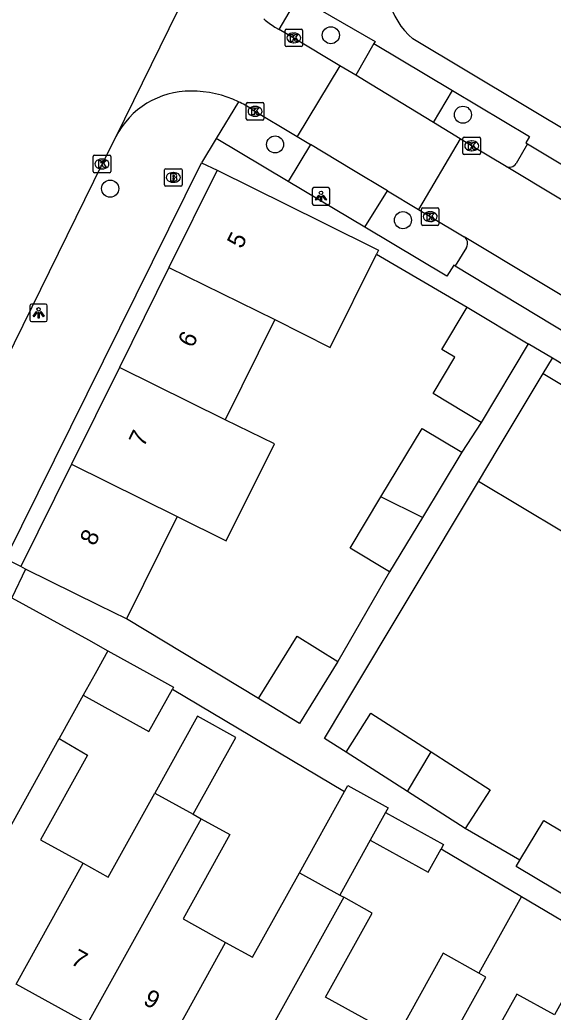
# Model space of a CAD drawing. Extents: x 160107 to 160928, y 382056 to 382918.
# Drawn here: x 160321.6 to 160352.1, y 382230.6 to 382287.4 of the extents above; entities that cross this region are included whole.
import ezdxf

# ---------------------------------------------------------------- set-up
doc = ezdxf.new("R2010")
doc.units = 0
for name, color, linetype in [('IMGEO_Boom', 7, 'Continuous'), ('IMGEO_Brandkraan', 7, 'Continuous'), ('IMGEO_Kolk', 7, 'Continuous'), ('IMGEO_Lichtpunt', 7, 'Continuous'), ('IMGEO_Muur', 7, 'Continuous'), ('IMGEO_Pand', 7, 'Continuous'), ('IMGEO_Pand_nummerreeks', 7, 'Continuous'), ('IMGEO_Parkeervlak_open', 7, 'Continuous'), ('IMGEO_Rijbaan_lokaal_open', 7, 'Continuous'), ('IMGEO_Voetpad_open', 7, 'Continuous')]:
    doc.layers.add(name, color=color, linetype=linetype)

msp = doc.modelspace()

# ---------------------------------------------------------------- linework, layer by layer
at = {"layer": 'IMGEO_Boom'}
for centre in [(160339.343, 382286.565), (160346.897, 382282.014), (160336.154, 382280.313), (160326.723, 382277.781), (160343.466, 382275.976)]:
    msp.add_circle(centre, 0.489, dxfattribs=at)
at = {"layer": 'IMGEO_Brandkraan'}
for p, q in [((160329.833, 382277.998), (160329.833, 382278.85)), ((160329.908, 382278.924), (160330.76, 382278.924)), ((160330.321, 382278.704), (160330.346, 382278.704)), ((160330.834, 382278.85), (160330.834, 382277.998)), ((160330.344, 382278.144), (160330.319, 382278.144)), ((160330.76, 382277.924), (160329.908, 382277.924))]:
    msp.add_line(p, q, dxfattribs=at)
for points in [[(160329.833, 382277.998), (160329.833, 382278.85)], [(160329.908, 382278.924), (160330.76, 382278.924)], [(160330.181, 382278.624), (160330.181, 382278.224), (160330.394, 382278.224)], [(160330.412, 382278.624), (160330.181, 382278.624)], [(160330.36, 382278.543), (160330.306, 382278.543), (160330.306, 382278.467)], [(160330.834, 382278.85), (160330.834, 382277.998)], [(160330.306, 382278.467), (160330.359, 382278.467)], [(160330.368, 382278.391), (160330.306, 382278.391), (160330.306, 382278.31)], [(160330.306, 382278.31), (160330.368, 382278.31)], [(160330.76, 382277.924), (160329.908, 382277.924)]]:
    msp.add_lwpolyline(points, dxfattribs=at)
for centre, radius, start, end in [((160329.91, 382278.848), 0.0765, 91.552, 178.448), ((160329.91, 382278.848), 0.0765, 91.552, 178.448), ((160330.361, 382278.505), 0.0379, 267.8285, 90.9355), ((160330.416, 382278.479), 0.145, 59.4692, 91.5367), ((160330.441, 382278.526), 0.0922, 285.5137, 58.1501), ((160330.758, 382278.848), 0.0765, 1.552, 88.448), ((160330.758, 382278.848), 0.0765, 1.552, 88.448), ((160329.91, 382278), 0.0765, 181.552, 268.448), ((160329.91, 382278), 0.0765, 181.552, 268.448), ((160330.369, 382278.35), 0.0404, 269.8759, 90.5077), ((160330.4, 382278.475), 0.251, 268.6676, 293.5347), ((160330.446, 382278.334), 0.105, 301.3115, 78.989), ((160330.758, 382278), 0.0765, 271.552, 358.448), ((160330.758, 382278), 0.0765, 271.552, 358.448)]:
    msp.add_arc(centre, radius, start, end, dxfattribs=at)
for centre, major_axis, ratio, start_param, end_param in [((160330.32, 382278.424), (-0.387, 0.002), 0.722429, 4.712389, 7.853982), ((160330.345, 382278.424), (-0.39, 0.002), 0.717154, 1.570796, 4.712389)]:
    msp.add_ellipse(centre, major_axis=major_axis, ratio=ratio, start_param=start_param, end_param=end_param, dxfattribs=at)
at = {"layer": 'IMGEO_Kolk'}
for p, q in [((160336.722, 382285.986), (160336.722, 382286.838)), ((160336.797, 382286.912), (160337.649, 382286.912)), ((160337.21, 382286.692), (160337.235, 382286.692)), ((160337.723, 382286.838), (160337.723, 382285.986)), ((160337.649, 382285.912), (160336.797, 382285.912)), ((160337.233, 382286.132), (160337.208, 382286.132)), ((160334.507, 382281.781), (160334.507, 382282.633)), ((160334.582, 382282.707), (160335.434, 382282.707)), ((160334.995, 382282.487), (160335.02, 382282.487)), ((160335.508, 382282.633), (160335.508, 382281.781)), ((160335.018, 382281.927), (160334.993, 382281.927)), ((160335.434, 382281.707), (160334.582, 382281.707)), ((160346.896, 382279.804), (160346.896, 382280.656)), ((160346.971, 382280.73), (160347.823, 382280.73)), ((160347.384, 382280.51), (160347.409, 382280.51)), ((160347.897, 382280.656), (160347.897, 382279.804)), ((160325.827, 382279.694), (160326.679, 382279.694)), ((160347.823, 382279.73), (160346.971, 382279.73)), ((160347.407, 382279.95), (160347.382, 382279.95)), ((160325.752, 382278.768), (160325.752, 382279.62)), ((160326.24, 382279.474), (160326.265, 382279.474)), ((160326.753, 382279.62), (160326.753, 382278.768)), ((160326.679, 382278.694), (160325.827, 382278.694)), ((160326.263, 382278.914), (160326.238, 382278.914)), ((160344.524, 382275.754), (160344.524, 382276.606)), ((160344.599, 382276.68), (160345.451, 382276.68)), ((160345.012, 382276.46), (160345.037, 382276.46)), ((160345.525, 382276.606), (160345.525, 382275.754)), ((160345.451, 382275.68), (160344.599, 382275.68)), ((160345.035, 382275.9), (160345.01, 382275.9))]:
    msp.add_line(p, q, dxfattribs=at)
for points in [[(160336.722, 382285.986), (160336.722, 382286.838)], [(160336.797, 382286.912), (160337.649, 382286.912)], [(160337.043, 382286.612), (160337.166, 382286.612), (160337.166, 382286.461), (160337.296, 382286.612), (160337.46, 382286.612), (160337.314, 382286.461), (160337.467, 382286.212), (160337.315, 382286.212), (160337.23, 382286.376), (160337.166, 382286.309), (160337.166, 382286.212), (160337.043, 382286.212), (160337.043, 382286.612)], [(160337.723, 382286.838), (160337.723, 382285.986)], [(160337.649, 382285.912), (160336.797, 382285.912)], [(160334.507, 382281.781), (160334.507, 382282.633)], [(160334.582, 382282.707), (160335.434, 382282.707)], [(160335.508, 382282.633), (160335.508, 382281.781)], [(160334.828, 382282.407), (160334.951, 382282.407), (160334.951, 382282.256), (160335.081, 382282.407), (160335.245, 382282.407), (160335.099, 382282.256), (160335.252, 382282.007), (160335.1, 382282.007), (160335.015, 382282.171), (160334.951, 382282.104), (160334.951, 382282.007), (160334.828, 382282.007), (160334.828, 382282.407)], [(160335.434, 382281.707), (160334.582, 382281.707)], [(160346.896, 382279.804), (160346.896, 382280.656)], [(160346.971, 382280.73), (160347.823, 382280.73)], [(160347.217, 382280.43), (160347.34, 382280.43), (160347.34, 382280.279), (160347.47, 382280.43), (160347.634, 382280.43), (160347.488, 382280.279), (160347.641, 382280.03), (160347.489, 382280.03), (160347.404, 382280.194), (160347.34, 382280.127), (160347.34, 382280.03), (160347.217, 382280.03), (160347.217, 382280.43)], [(160347.897, 382280.656), (160347.897, 382279.804)], [(160325.827, 382279.694), (160326.679, 382279.694)], [(160347.823, 382279.73), (160346.971, 382279.73)], [(160325.752, 382278.768), (160325.752, 382279.62)], [(160326.073, 382279.394), (160326.196, 382279.394), (160326.196, 382279.243), (160326.326, 382279.394), (160326.49, 382279.394), (160326.344, 382279.243), (160326.497, 382278.994), (160326.345, 382278.994), (160326.26, 382279.158), (160326.196, 382279.091), (160326.196, 382278.994), (160326.073, 382278.994), (160326.073, 382279.394)], [(160326.753, 382279.62), (160326.753, 382278.768)], [(160326.679, 382278.694), (160325.827, 382278.694)], [(160344.524, 382275.754), (160344.524, 382276.606)], [(160344.599, 382276.68), (160345.451, 382276.68)], [(160344.845, 382276.38), (160344.968, 382276.38), (160344.968, 382276.229), (160345.098, 382276.38), (160345.262, 382276.38), (160345.116, 382276.229), (160345.269, 382275.98), (160345.117, 382275.98), (160345.032, 382276.144), (160344.968, 382276.077), (160344.968, 382275.98), (160344.845, 382275.98), (160344.845, 382276.38)], [(160345.525, 382276.606), (160345.525, 382275.754)], [(160345.451, 382275.68), (160344.599, 382275.68)]]:
    msp.add_lwpolyline(points, dxfattribs=at)
for centre, start, end in [((160336.799, 382286.836), 91.552, 178.448), ((160336.799, 382286.836), 91.552, 178.448), ((160337.647, 382286.836), 1.552, 88.448), ((160337.647, 382286.836), 1.552, 88.448), ((160336.799, 382285.988), 181.552, 268.448), ((160336.799, 382285.988), 181.552, 268.448), ((160337.647, 382285.988), 271.552, 358.448), ((160337.647, 382285.988), 271.552, 358.448), ((160334.584, 382282.631), 91.552, 178.448), ((160334.584, 382282.631), 91.552, 178.448), ((160335.432, 382282.631), 1.552, 88.448), ((160335.432, 382282.631), 1.552, 88.448), ((160334.584, 382281.783), 181.552, 268.448), ((160334.584, 382281.783), 181.552, 268.448), ((160335.432, 382281.783), 271.552, 358.448), ((160335.432, 382281.783), 271.552, 358.448), ((160346.973, 382280.654), 91.552, 178.448), ((160346.973, 382280.654), 91.552, 178.448), ((160347.821, 382280.654), 1.552, 88.448), ((160347.821, 382280.654), 1.552, 88.448), ((160325.829, 382279.618), 91.552, 178.448), ((160325.829, 382279.618), 91.552, 178.448), ((160326.677, 382279.618), 1.552, 88.448), ((160326.677, 382279.618), 1.552, 88.448), ((160346.973, 382279.806), 181.552, 268.448), ((160346.973, 382279.806), 181.552, 268.448), ((160347.821, 382279.806), 271.552, 358.448), ((160347.821, 382279.806), 271.552, 358.448), ((160325.829, 382278.77), 181.552, 268.448), ((160325.829, 382278.77), 181.552, 268.448), ((160326.677, 382278.77), 271.552, 358.448), ((160326.677, 382278.77), 271.552, 358.448), ((160344.601, 382276.604), 91.552, 178.448), ((160344.601, 382276.604), 91.552, 178.448), ((160345.449, 382276.604), 1.552, 88.448), ((160345.449, 382276.604), 1.552, 88.448), ((160344.601, 382275.756), 181.552, 268.448), ((160344.601, 382275.756), 181.552, 268.448), ((160345.449, 382275.756), 271.552, 358.448), ((160345.449, 382275.756), 271.552, 358.448)]:
    msp.add_arc(centre, 0.0765, start, end, dxfattribs=at)
for centre, major_axis, ratio, start_param, end_param in [((160337.209, 382286.412), (-0.387, 0.002), 0.722429, 4.712389, 7.853982), ((160337.234, 382286.412), (-0.39, 0.002), 0.717154, 1.570796, 4.712389), ((160334.994, 382282.207), (-0.387, 0.002), 0.722429, 4.712389, 7.853982), ((160335.019, 382282.207), (-0.39, 0.002), 0.717154, 1.570796, 4.712389), ((160347.383, 382280.23), (-0.387, 0.002), 0.722429, 4.712389, 7.853982), ((160347.408, 382280.23), (-0.39, 0.002), 0.717154, 1.570796, 4.712389), ((160326.239, 382279.194), (-0.387, 0.002), 0.722429, 4.712389, 7.853982), ((160326.264, 382279.194), (-0.39, 0.002), 0.717154, 1.570796, 4.712389), ((160345.011, 382276.18), (-0.387, 0.002), 0.722429, 4.712389, 7.853982), ((160345.036, 382276.18), (-0.39, 0.002), 0.717154, 1.570796, 4.712389)]:
    msp.add_ellipse(centre, major_axis=major_axis, ratio=ratio, start_param=start_param, end_param=end_param, dxfattribs=at)
at = {"layer": 'IMGEO_Lichtpunt'}
for p, q in [((160338.28, 382277.743), (160338.28, 382276.936)), ((160338.28, 382277.743), (160338.28, 382276.936)), ((160339.182, 382277.838), (160338.374, 382277.838)), ((160339.182, 382277.838), (160338.374, 382277.838)), ((160339.276, 382276.936), (160339.276, 382277.743)), ((160339.276, 382276.936), (160339.276, 382277.743)), ((160338.374, 382276.842), (160339.182, 382276.842)), ((160338.374, 382276.842), (160339.182, 382276.842)), ((160323.031, 382271.171), (160322.223, 382271.171)), ((160323.031, 382271.171), (160322.223, 382271.171)), ((160322.129, 382271.076), (160322.129, 382270.269)), ((160322.129, 382271.076), (160322.129, 382270.269)), ((160323.125, 382270.269), (160323.125, 382271.076)), ((160323.125, 382270.269), (160323.125, 382271.076)), ((160322.223, 382270.175), (160323.031, 382270.175)), ((160322.223, 382270.175), (160323.031, 382270.175))]:
    msp.add_line(p, q, dxfattribs=at)
for points in [[(160338.654, 382277.407), (160338.693, 382277.379), (160338.505, 382277.117), (160338.467, 382277.144), (160338.654, 382277.407)], [(160338.756, 382277.359), (160338.803, 382277.359), (160338.803, 382277.037), (160338.756, 382277.037), (160338.756, 382277.359)], [(160338.866, 382277.379), (160338.904, 382277.406), (160339.091, 382277.144), (160339.052, 382277.116), (160338.866, 382277.379)], [(160322.503, 382270.74), (160322.542, 382270.712), (160322.354, 382270.45), (160322.316, 382270.477), (160322.503, 382270.74)], [(160322.605, 382270.692), (160322.652, 382270.692), (160322.652, 382270.37), (160322.605, 382270.37), (160322.605, 382270.692)], [(160322.715, 382270.712), (160322.753, 382270.739), (160322.94, 382270.477), (160322.901, 382270.449), (160322.715, 382270.712)]]:
    msp.add_lwpolyline(points, dxfattribs=at)
for centre in [(160338.779, 382277.541), (160322.628, 382270.874)]:
    msp.add_circle(centre, 0.0994, dxfattribs=at)
for centre, start, end in [((160338.374, 382277.743), 90, 180), ((160338.374, 382277.743), 90, 180), ((160339.182, 382277.743), 0, 90), ((160339.182, 382277.743), 0, 90), ((160338.374, 382276.936), 180, 270), ((160338.374, 382276.936), 180, 270), ((160339.182, 382276.936), 270, 0), ((160339.182, 382276.936), 270, 360), ((160322.223, 382271.076), 90, 180), ((160322.223, 382271.076), 90, 180), ((160323.031, 382271.076), 0, 90), ((160323.031, 382271.076), 0, 90), ((160322.223, 382270.269), 180, 270), ((160322.223, 382270.269), 180, 270), ((160323.031, 382270.269), 270, 0), ((160323.031, 382270.269), 270, 360)]:
    msp.add_arc(centre, 0.0946, start, end, dxfattribs=at)
at = {"layer": 'IMGEO_Muur'}
msp.add_lwpolyline([(160341.955, 382274.034), (160347.132, 382270.997)], dxfattribs=at)
at = {"layer": 'IMGEO_Pand'}
for points in [[(160332.834, 382278.83), (160330.086, 382273.276)], [(160332.834, 382278.83), (160338.878, 382275.84), (160342.068, 382274.262), (160341.955, 382274.034)], [(160336.13, 382270.285), (160339.307, 382268.679), (160341.955, 382274.034)], [(160330.086, 382273.276), (160327.247, 382267.537)], [(160330.086, 382273.276), (160336.13, 382270.285)], [(160347.932, 382264.399), (160345.187, 382266.044), (160346.433, 382268.124), (160345.681, 382268.574), (160347.132, 382270.997)], [(160347.132, 382270.997), (160350.629, 382268.903)], [(160336.13, 382270.285), (160333.29, 382264.546)], [(160350.629, 382268.903), (160347.932, 382264.399)], [(160327.247, 382267.537), (160324.506, 382261.998)], [(160333.29, 382264.546), (160327.247, 382267.537)], [(160347.79, 382261.014), (160348.919, 382262.9), (160351.487, 382267.189)], [(160351.487, 382267.189), (160356.34, 382264.274)], [(160330.55, 382259.008), (160333.364, 382257.616), (160336.114, 382263.173), (160333.29, 382264.546)], [(160342.21, 382260.131), (160344.573, 382264.055), (160346.825, 382262.699)], [(160346.825, 382262.699), (160344.575, 382258.961)], [(160324.506, 382261.998), (160321.607, 382256.138)], [(160324.506, 382261.998), (160330.55, 382259.008)], [(160352.635, 382258.104), (160347.79, 382261.014)], [(160342.7, 382255.846), (160340.447, 382257.203), (160342.21, 382260.131)], [(160344.575, 382258.961), (160342.21, 382260.131)], [(160330.55, 382259.008), (160327.651, 382253.148)], [(160344.575, 382258.961), (160342.7, 382255.846)], [(160321.884, 382256.001), (160321.607, 382256.138)], [(160327.651, 382253.148), (160326.089, 382253.921), (160321.884, 382256.001)], [(160321.096, 382254.355), (160325.475, 382251.94), (160326.589, 382251.322)], [(160335.212, 382248.593), (160337.408, 382252.152), (160339.743, 382250.711)], [(160326.589, 382251.322), (160325.857, 382250), (160325.183, 382248.784)], [(160326.589, 382251.322), (160328.978, 382250), (160330.349, 382249.241), (160330.284, 382249.125)], [(160339.743, 382250.711), (160337.547, 382247.152), (160335.212, 382248.593)], [(160325.183, 382248.784), (160328.942, 382246.703), (160330.284, 382249.125)], [(160325.183, 382248.784), (160323.812, 382246.308)], [(160331.469, 382241.958), (160333.911, 382246.366), (160331.718, 382247.582), (160329.276, 382243.174)], [(160340.21, 382245.518), (160341.638, 382247.743), (160345.085, 382245.531)], [(160317.268, 382234.495), (160323.812, 382246.308)], [(160323.812, 382246.308), (160325.421, 382245.338), (160322.742, 382240.502), (160325.176, 382239.154)], [(160343.724, 382243.264), (160340.21, 382245.518)], [(160343.724, 382243.264), (160345.085, 382245.531)], [(160345.085, 382245.531), (160348.455, 382243.37), (160347.027, 382241.145)], [(160337.544, 382238.612), (160340.126, 382243.273)], [(160340.126, 382243.273), (160340.31, 382243.606), (160342.617, 382242.329), (160342.474, 382242.07)], [(160325.176, 382239.154), (160326.609, 382238.36), (160329.276, 382243.174)], [(160329.276, 382243.174), (160331.469, 382241.958)], [(160347.027, 382241.145), (160343.724, 382243.264)], [(160331.919, 382241.709), (160325.421, 382229.978)], [(160331.919, 382241.709), (160333.562, 382240.799), (160330.89, 382235.976), (160333.324, 382234.628)], [(160331.469, 382241.958), (160331.919, 382241.709)], [(160342.474, 382242.07), (160341.593, 382240.481)], [(160342.474, 382242.07), (160345.781, 382240.239), (160345.644, 382239.992)], [(160350.155, 382239.337), (160351.52, 382241.611), (160354.874, 382239.597)], [(160341.593, 382240.481), (160339.849, 382237.335)], [(160341.593, 382240.481), (160344.901, 382238.649), (160345.644, 382239.992)], [(160353.294, 382236.966), (160349.94, 382238.98), (160350.155, 382239.337)], [(160321.345, 382232.236), (160325.176, 382239.154)], [(160333.324, 382234.628), (160334.865, 382233.774), (160337.544, 382238.612)], [(160337.544, 382238.612), (160339.849, 382237.335)], [(160340.08, 382237.207), (160333.574, 382225.462)], [(160341.487, 382230.13), (160339.044, 382231.483), (160341.714, 382236.302), (160340.08, 382237.207)], [(160339.849, 382237.335), (160340.08, 382237.207)], [(160350.245, 382237.256), (160347.812, 382232.862)], [(160350.245, 382237.256), (160354.49, 382234.732)], [(160329.498, 382227.72), (160333.324, 382234.628)], [(160354.49, 382234.732), (160352.129, 382230.47), (160349.972, 382231.666), (160347.333, 382226.903), (160350.081, 382225.38)], [(160347.812, 382232.862), (160345.759, 382234), (160343.116, 382229.228), (160341.487, 382230.13)], [(160341.726, 382220.946), (160348.206, 382232.644), (160347.812, 382232.862)], [(160325.421, 382229.978), (160321.345, 382232.236)]]:
    msp.add_lwpolyline(points, dxfattribs=at)
at = {"layer": 'IMGEO_Parkeervlak_open'}
for points in [[(160341.806, 382286.094), (160340.765, 382284.275)], [(160345.22, 382281.56), (160346.308, 382283.398)], [(160338.171, 382280.311), (160336.896, 382278.195)], [(160350.59, 382280.346), (160349.933, 382279.221)], [(160341.281, 382275.572), (160342.575, 382277.658)], [(160347.093, 382274.42), (160346.443, 382273.357)]]:
    msp.add_lwpolyline(points, dxfattribs=at)
for centre, radius, start, end in [((160349.559, 382279.449), 0.438, 243.0717, 328.687), ((160346.707, 382274.659), 0.454, 328.2653, 54.427)]:
    msp.add_arc(centre, radius, start, end, dxfattribs=at)
at = {"layer": 'IMGEO_Rijbaan_lokaal_open'}
for points in [[(160333.608, 382294.147), (160327.052, 382280.751)], [(160336.146, 382287.034), (160336.386, 382286.893)], [(160339.856, 382284.821), (160337.221, 382286.404), (160336.386, 382286.893)], [(160339.856, 382284.821), (160337.415, 382280.765)], [(160340.765, 382284.275), (160339.856, 382284.821)], [(160345.22, 382281.56), (160341.605, 382283.77), (160340.765, 382284.275)], [(160334.811, 382282.332), (160337.415, 382280.765)], [(160346.737, 382280.632), (160345.22, 382281.56)], [(160337.415, 382280.765), (160338.171, 382280.311)], [(160327.052, 382280.751), (160326.263, 382279.198), (160315.659, 382257.61)], [(160342.575, 382277.658), (160340.545, 382278.882), (160338.171, 382280.311)], [(160346.737, 382280.632), (160344.356, 382276.584)], [(160349.36, 382279.058), (160347.392, 382280.232), (160346.737, 382280.632)], [(160355.526, 382275.346), (160355.493, 382275.363), (160349.36, 382279.058)], [(160342.575, 382277.658), (160344.356, 382276.584)], [(160344.356, 382276.584), (160345.027, 382276.18), (160346.971, 382275.028)], [(160370.614, 382260.795), (160363.396, 382265.134), (160346.971, 382275.028)]]:
    msp.add_lwpolyline(points, dxfattribs=at)
for centre, radius, start, end in [((160338.744, 382291.288), 4.984, 229.4614, 238.5901), ((160331.295, 382278.611), 4.752, 89.3956, 153.2398), ((160331.409, 382277.236), 6.127, 64.2952, 90.6026), ((160331.447, 382277.307), 6.047, 56.201, 64.3259)]:
    msp.add_arc(centre, radius, start, end, dxfattribs=at)
at = {"layer": 'IMGEO_Voetpad_open'}
for points in [[(160336.386, 382286.893), (160337.48, 382288.767), (160341.872, 382286.209), (160341.806, 382286.094)], [(160341.806, 382286.094), (160346.308, 382283.398)], [(160356.664, 382278.779), (160344.039, 382286.352)], [(160346.308, 382283.398), (160350.694, 382280.772), (160350.485, 382280.409), (160350.59, 382280.346)], [(160334.067, 382282.757), (160332.788, 382280.651)], [(160332.788, 382280.651), (160331.943, 382279.258)], [(160336.896, 382278.195), (160332.788, 382280.651)], [(160350.59, 382280.346), (160356.055, 382277.065)], [(160321.607, 382256.138), (160320.744, 382256.583), (160331.943, 382279.258)], [(160331.943, 382279.258), (160332.834, 382278.83)], [(160341.281, 382275.572), (160336.896, 382278.195)], [(160346.443, 382273.357), (160346.381, 382273.394), (160345.979, 382272.763), (160341.281, 382275.572)], [(160341.955, 382274.034), (160347.132, 382270.997)], [(160346.443, 382273.357), (160353.864, 382268.87), (160368.706, 382259.906), (160371.786, 382258.051), (160387.002, 382248.878), (160392.646, 382245.482), (160401.49, 382240.126), (160401.767, 382240.616)], [(160352.016, 382268.075), (160350.629, 382268.903)], [(160351.487, 382267.189), (160352.016, 382268.075)], [(160401.443, 382238.222), (160387.269, 382246.785), (160368.972, 382257.814), (160352.016, 382268.075)], [(160347.932, 382264.399), (160346.825, 382262.699)], [(160340.21, 382245.518), (160338.984, 382246.304), (160340.091, 382248.153), (160347.79, 382261.014)], [(160321.884, 382256.001), (160321.096, 382254.355)], [(160342.7, 382255.846), (160339.743, 382250.711)], [(160335.212, 382248.593), (160327.651, 382253.148)], [(160330.284, 382249.125), (160340.126, 382243.273)], [(160350.155, 382239.337), (160347.027, 382241.145)], [(160345.644, 382239.992), (160350.245, 382237.256)]]:
    msp.add_lwpolyline(points, dxfattribs=at)
msp.add_arc((160346.674, 382289.5), 4.105, 156.0568, 230.0697, dxfattribs=at)

# ---------------------------------------------------------------- texts
at = {"layer": 'IMGEO_Pand_nummerreeks'}
for s, rotation, p in [('5', 63.6785, (160334.248, 382274.293)), ('6', 63.6785, (160331.441, 382268.62)), ('7', 63.6785, (160328.634, 382262.947)), ('8', 63.6758, (160325.831, 382257.276)), ('7', 331.0141, (160324.404, 382233.422)), ('9', 331.0155, (160328.551, 382231.125))]:
    msp.add_text(s, height=1, rotation=rotation, dxfattribs=at).set_placement(p)

doc.saveas('drawing.dxf')
